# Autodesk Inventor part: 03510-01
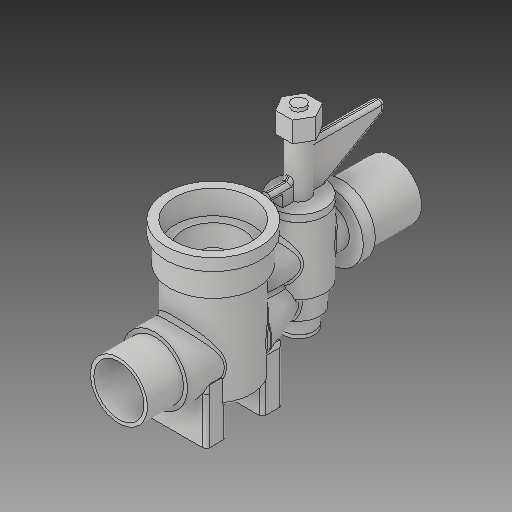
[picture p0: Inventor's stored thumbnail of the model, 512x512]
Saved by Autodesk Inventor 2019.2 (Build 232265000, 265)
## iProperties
Created: 2021-08
Part Number: 03510-01
Material: Generic
Document SubType Name: Modeling
Designer: Lenora
Density: 1 g/cm^3
Appearance: Default
Author: Lenora
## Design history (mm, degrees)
derived "03510-2.ipt"
feature "Solid1::03510-2.ipt"
feature "Solid2::03510-2.ipt"
feature "Solid3::03510-2.ipt"
tag "TaggingFeature1"
body "Solid1"
body "Solid2"
body "Solid3"
other parameters: "d1" = 21, "d4" = 33.249, "d5" = 38, "d6" = 15, "d7" = 55, "d8" = 55, "d9" = 2, "d10" = 2, "d11" = 44.845, "d12" = 5, "d13" = 5, "d14" = 5, "d16" = 1, "d17" = 1, "d20" = 15, "d21" = 15, "d22" = 14, "d23" = 14, "d24" = 12, "d25" = 7, "d26" = 6, "d27" = 37, "d30" = 3, "d31" = 3, "d32" = 3, "d33" = 18, "d34" = 2, "d35" = 7, "d36" = 43, "d38" = 2, "d40" = 59, "d41" = 33.249, "d42" = 7, "d44" = 3, "d45" = 2, "d46" = 5, "d47" = 4, "d48" = 4, "d50" = 12, "d51" = 2, "d52" = 4, "d59" = 7, "d60" = 6, "d61" = 43, "d62" = 5, "d63" = 7, "d64" = 5, "d65" = 30 deg, "d66" = 50 deg, "d67" = 3, "d68" = 5, "d69" = 0, "d70" = 23, "d72" = 0, "d75" = 7, "d80" = 0, "d82" = 0, "d83" = 3, "d85" = 0, "d86" = 37, "d87" = 12, "d88" = 0, "d90" = 360 deg, "d95" = 5, "d97" = 0, "d98" = 2
